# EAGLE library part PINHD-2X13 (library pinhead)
PIN HEADER
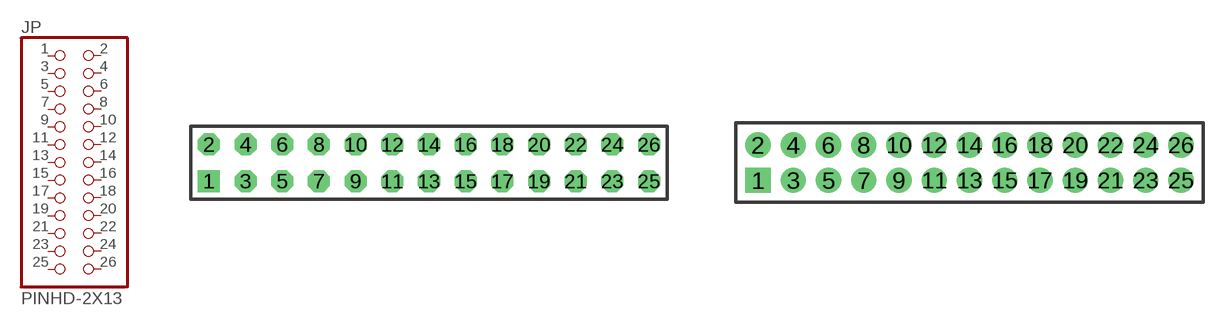
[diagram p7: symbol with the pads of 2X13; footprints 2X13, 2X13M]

Designator prefix JP

## PINHD-2X13  [2X13]
1  1  pas
2  2  pas
3  3  pas
4  4  pas
5  5  pas
6  6  pas
7  7  pas
8  8  pas
9  9  pas
10  10  pas
11  11  pas
12  12  pas
13  13  pas
14  14  pas
15  15  pas
16  16  pas
17  17  pas
18  18  pas
19  19  pas
20  20  pas
21  21  pas
22  22  pas
23  23  pas
24  24  pas
25  25  pas
26  26  pas

## PINHD-2X13M  [2X13M]
Pads as for 2X13

## Footprint 2X13 (pad centres in mm)
PIN HEADER - 0.1"
drill 1.016 square: 1 -15.24,-1.27
drill 1.016 octagon: 2 -15.24,1.27; 3 -12.7,-1.27; 4 -12.7,1.27; 5 -10.16,-1.27; 6 -10.16,1.27; 7 -7.62,-1.27; 8 -7.62,1.27; 9 -5.08,-1.27; 10 -5.08,1.27; 11 -2.54,-1.27; 12 -2.54,1.27; 13 0,-1.27; 14 0,1.27; 15 2.54,-1.27; 16 2.54,1.27; 17 5.08,-1.27; 18 5.08,1.27; 19 7.62,-1.27; 20 7.62,1.27; 21 10.16,-1.27; 22 10.16,1.27; 23 12.7,-1.27; 24 12.7,1.27; 25 15.24,-1.27; 26 15.24,1.27

## Footprint 2X13M (pad centres in mm)
PIN HEADER - 2MM"
drill 0.914 square: 1 -12,-1
drill 0.914 round: 2 -12,1; 3 -10,-1; 4 -10,1; 5 -8,-1; 6 -8,1; 7 -6,-1; 8 -6,1; 9 -4,-1; 10 -4,1; 11 -2,-1; 12 -2,1; 13 0,-1; 14 0,1; 15 2,-1; 16 2,1; 17 4,-1; 18 4,1; 19 6,-1; 20 6,1; 21 8,-1; 22 8,1; 23 10,-1; 24 10,1; 25 12,-1; 26 12,1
